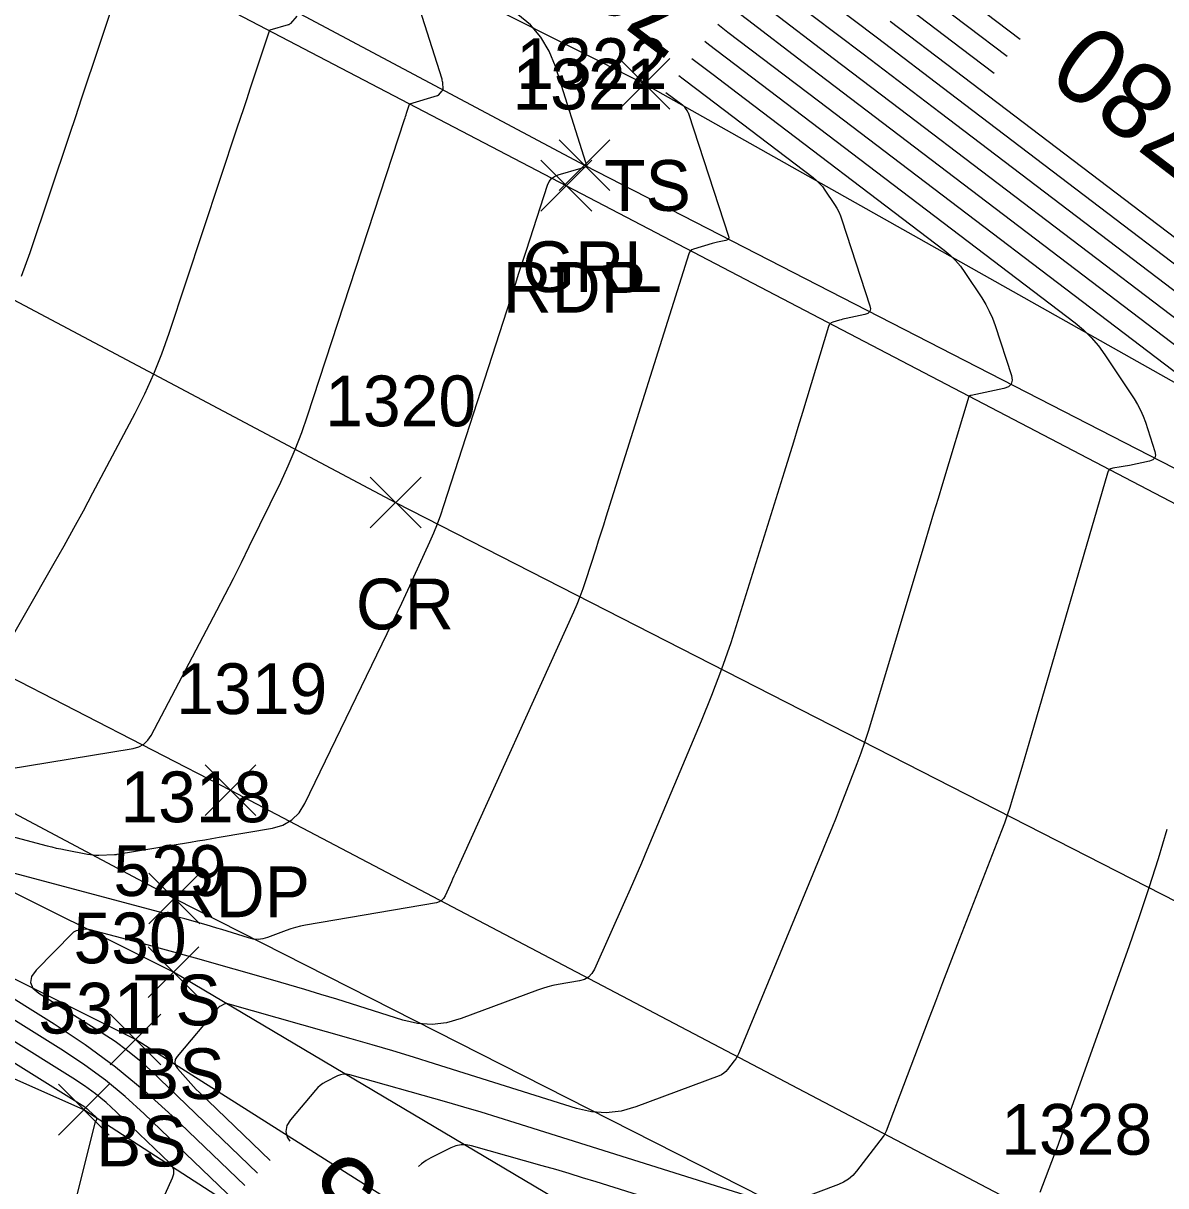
# Model space of a CAD drawing. Extents: x 1650836 to 1652450, y 332578 to 333908.
# Drawn here: x 1652324.34 to 1652369.33, y 332642.95 to 332688.73 of the extents above; entities that cross this region are included whole.
import ezdxf

# ---------------------------------------------------------------- set-up
doc = ezdxf.new("R2010")
doc.units = 0
for name, color, linetype in [('L_A', 7, 'Continuous'), ('L_I', 7, 'Continuous'), ('L_TIC', 7, 'Continuous'), ('LAWA', 7, 'Continuous'), ('LELB', 7, 'Continuous'), ('LSOGCMA', 7, 'Continuous'), ('LSOGCMA_T', 7, 'Continuous'), ('LSOGCMI', 7, 'Continuous'), ('P_A', 7, 'Continuous'), ('P_I', 7, 'Continuous'), ('P_TIC', 7, 'Continuous'), ('PET', 7, 'Continuous'), ('PRC', 7, 'Continuous'), ('R_A', 7, 'Continuous'), ('R_I', 7, 'Continuous'), ('R_TIC', 7, 'Continuous'), ('RGR', 7, 'Continuous')]:
    doc.layers.add(name, color=color, linetype=linetype)

msp = doc.modelspace()

# ---------------------------------------------------------------- linework, layer by layer
at = {"layer": 'L_TIC'}
for points in [[(1652347.8, 332685.345), (1652349.8, 332687.345)], [(1652349.8, 332685.345), (1652347.8, 332687.345)], [(1652329.286, 332653.264), (1652331.286, 332655.264)], [(1652331.286, 332653.264), (1652329.286, 332655.264)], [(1652329.255, 332650.361), (1652331.255, 332652.361)], [(1652331.255, 332650.361), (1652329.255, 332652.361)], [(1652327.76, 332647.708), (1652329.76, 332649.708)], [(1652329.76, 332647.708), (1652327.76, 332649.708)], [(1652325.723, 332644.943), (1652327.723, 332646.943)], [(1652327.723, 332644.943), (1652325.723, 332646.943)]]:
    msp.add_lwpolyline(points, dxfattribs=at)
at = {"layer": 'LAWA'}
msp.add_lwpolyline([(1652377.083, 332609.462), (1652362.423, 332618.359), (1652352.896, 332629.018), (1652326.723, 332645.943), (1652287.129, 332663.549), (1652263.425, 332671.343), (1652249.055, 332682.968), (1652227.219, 332684.809), (1652198.28, 332683.973), (1652188.25, 332681.448)], dxfattribs=at)
at = {"layer": 'LELB'}
for points in [[(1652023.441, 332859.649), (1652034.235, 332853.429), (1652052.246, 332842.357), (1652084.686, 332826.36), (1652123.711, 332804.04), (1652160.81, 332785.384), (1652195.281, 332767.897), (1652235.573, 332746.682), (1652255.289, 332735.81), (1652296.57, 332712.591), (1652348.8, 332686.345), (1652380.841, 332668.301), (1652404.073, 332656.539)], [(1652226.417, 332702.923), (1652236.723, 332699.587), (1652280.373, 332680.816), (1652330.286, 332654.264), (1652363.786, 332637.255), (1652386.916, 332625.064)], [(1652382.141, 332616.979), (1652358.657, 332634.506), (1652330.255, 332651.361), (1652290.321, 332671.283), (1652269.989, 332681.007), (1652251.521, 332688.043), (1652226.806, 332692.532), (1652196.733, 332693.642), (1652183.53, 332688.882)], [(1652365.04, 332620.431), (1652356.315, 332631.256), (1652328.76, 332648.708), (1652289.164, 332668.483), (1652266.826, 332677.17), (1652249.055, 332682.968)]]:
    msp.add_lwpolyline(points, dxfattribs=at)
at = {"layer": 'LSOGCMA'}
for points in [[(1652351.174, 332688.023), (1652351.321, 332687.911), (1652352.688, 332686.871), (1652354.055, 332685.831), (1652365.761, 332676.93), (1652366.093, 332676.654), (1652366.399, 332676.354), (1652366.678, 332676.03), (1652366.931, 332675.68), (1652368.085, 332673.937), (1652368.219, 332673.718), (1652368.337, 332673.493), (1652368.44, 332673.26), (1652368.528, 332673.019), (1652368.906, 332671.862), (1652368.93, 332671.723), (1652368.902, 332671.614), (1652368.822, 332671.535), (1652368.689, 332671.486), (1652367.901, 332671.319), (1652367.819, 332671.302), (1652367.737, 332671.286), (1652367.655, 332671.271), (1652367.573, 332671.257), (1652367.244, 332671.204), (1652367.169, 332671.182), (1652367.109, 332671.143), (1652367.064, 332671.088), (1652367.033, 332671.017), (1652364.032, 332660.683), (1652363.94, 332660.368), (1652363.847, 332660.053), (1652363.754, 332659.738), (1652363.66, 332659.424), (1652363.285, 332658.166), (1652363.188, 332657.852), (1652363.084, 332657.541), (1652362.975, 332657.232), (1652362.859, 332656.924), (1652361.118, 332652.433), (1652360.831, 332651.689), (1652360.545, 332650.945), (1652360.26, 332650.201), (1652359.976, 332649.456), (1652358.32, 332645.096), (1652358.297, 332645.042), (1652358.271, 332644.989), (1652358.24, 332644.939), (1652358.206, 332644.891), (1652357.151, 332643.516), (1652357.001, 332643.347), (1652356.833, 332643.203), (1652356.646, 332643.084), (1652356.441, 332642.992), (1652354.838, 332642.395)], [(1652353.47, 332642.359), (1652343.712, 332645.427), (1652343.039, 332645.636), (1652342.364, 332645.841), (1652341.689, 332646.04), (1652341.012, 332646.235), (1652337.196, 332647.32), (1652337.071, 332647.343), (1652336.949, 332647.344), (1652336.83, 332647.32), (1652336.712, 332647.273), (1652336.248, 332647.036), (1652336.136, 332646.971), (1652336.032, 332646.897), (1652335.936, 332646.812), (1652335.848, 332646.717), (1652334.864, 332645.543), (1652334.721, 332645.315), (1652334.675, 332645.088), (1652334.727, 332644.863), (1652334.834, 332644.702)]]:
    msp.add_lwpolyline(points, dxfattribs=at)
at = {"layer": 'LSOGCMI'}
for points in [[(1652324.267, 332678.777), (1652324.604, 332679.706), (1652326.168, 332684.369), (1652326.401, 332685.066), (1652326.634, 332685.763), (1652326.866, 332686.46), (1652327.099, 332687.157), (1652328.479, 332691.305)], [(1652323.707, 332659.351), (1652328.661, 332660.175), (1652328.885, 332660.237), (1652329.078, 332660.343), (1652329.239, 332660.493), (1652329.369, 332660.686), (1652331.962, 332665.607), (1652332.288, 332666.233), (1652332.61, 332666.862), (1652332.926, 332667.492), (1652333.238, 332668.126), (1652334.474, 332670.664), (1652334.772, 332671.304), (1652335.047, 332671.952), (1652335.301, 332672.609), (1652335.532, 332673.275), (1652339.355, 332684.944), (1652339.375, 332685.006), (1652339.395, 332685.067), (1652339.415, 332685.129), (1652339.435, 332685.19), (1652339.552, 332685.55), (1652339.554, 332685.554), (1652339.557, 332685.557), (1652339.561, 332685.56), (1652339.565, 332685.562), (1652340.656, 332685.883), (1652340.669, 332685.888), (1652340.682, 332685.895), (1652340.693, 332685.903), (1652340.703, 332685.913), (1652340.825, 332686.056), (1652340.845, 332686.085), (1652340.859, 332686.115), (1652340.867, 332686.148), (1652340.868, 332686.183), (1652340.858, 332686.362), (1652340.854, 332686.404), (1652340.848, 332686.445), (1652340.839, 332686.486), (1652340.828, 332686.526), (1652339.757, 332689.916)], [(1652380.189, 332669.134), (1652358.847, 332685.363), (1652356.233, 332687.351), (1652353.62, 332689.34), (1652352.707, 332690.035)], [(1652376.091, 332674.367), (1652360.799, 332685.996), (1652357.975, 332688.144), (1652355.153, 332690.292)], [(1652359.485, 332690.171), (1652361.52, 332688.624), (1652363.081, 332687.437)], [(1652378.14, 332671.75), (1652360.444, 332685.207), (1652357.415, 332687.511), (1652354.387, 332689.816)], [(1652358.982, 332689.495), (1652361.279, 332687.748), (1652362.568, 332686.768)], [(1652361.76, 332689.499), (1652363.593, 332688.106)], [(1652315.11, 332659.045), (1652325.279, 332656.339), (1652325.458, 332656.293), (1652325.637, 332656.25), (1652325.818, 332656.211), (1652325.999, 332656.174), (1652326.867, 332656.007), (1652326.978, 332655.989), (1652327.089, 332655.977), (1652327.2, 332655.972), (1652327.313, 332655.972), (1652327.935, 332655.992), (1652327.961, 332655.993), (1652327.986, 332655.995), (1652328.012, 332655.998), (1652328.038, 332656.002), (1652330.922, 332656.482), (1652331.203, 332656.529), (1652331.483, 332656.576), (1652331.764, 332656.624), (1652332.045, 332656.672), (1652334.15, 332657.036), (1652334.563, 332657.154), (1652334.914, 332657.354), (1652335.204, 332657.636), (1652335.431, 332658.001), (1652339.077, 332665.544), (1652339.241, 332665.888), (1652339.404, 332666.233), (1652339.564, 332666.579), (1652339.723, 332666.925), (1652340.351, 332668.315), (1652340.503, 332668.664), (1652340.646, 332669.017), (1652340.778, 332669.374), (1652340.9, 332669.735), (1652343.535, 332677.888), (1652343.69, 332678.366), (1652343.845, 332678.845), (1652344, 332679.323), (1652344.155, 332679.801), (1652344.986, 332682.356), (1652345.05, 332682.499), (1652345.141, 332682.614), (1652345.259, 332682.702), (1652345.404, 332682.762), (1652346.307, 332683.028), (1652346.372, 332683.047), (1652346.528, 332683.093), (1652346.537, 332683.095), (1652346.539, 332683.096), (1652346.539, 332683.098), (1652346.509, 332683.189), (1652346.499, 332683.221), (1652346.489, 332683.252), (1652345.294, 332687.036), (1652345.05, 332687.641), (1652344.722, 332688.185), (1652344.307, 332688.666), (1652343.808, 332689.085)], [(1652335.109, 332689.018), (1652334.862, 332688.729), (1652334.842, 332688.709), (1652334.82, 332688.692), (1652334.795, 332688.678), (1652334.768, 332688.668), (1652334.051, 332688.457), (1652334.038, 332688.452), (1652334.028, 332688.444), (1652334.019, 332688.434), (1652334.014, 332688.421), (1652333.262, 332686.137), (1652333.135, 332685.752), (1652333.008, 332685.366), (1652332.881, 332684.981), (1652332.753, 332684.596), (1652330.073, 332676.508), (1652329.786, 332675.702), (1652329.468, 332674.909), (1652329.116, 332674.131), (1652328.732, 332673.367), (1652327.067, 332670.221), (1652326.694, 332669.523), (1652326.315, 332668.829), (1652325.93, 332668.138), (1652325.539, 332667.45), (1652323.353, 332663.638)], [(1652376.202, 332671.107), (1652357.25, 332685.519), (1652355.051, 332687.191), (1652352.854, 332688.864), (1652352.196, 332689.364)], [(1652351.685, 332688.694), (1652352.087, 332688.387), (1652353.87, 332687.031), (1652355.652, 332685.675), (1652370.917, 332674.067)], [(1652358.479, 332688.819), (1652361.039, 332686.872), (1652374.043, 332676.984)], [(1652350.663, 332687.352), (1652351.506, 332686.711), (1652352.457, 332685.987), (1652360.605, 332679.792), (1652360.836, 332679.6), (1652361.049, 332679.391), (1652361.243, 332679.165), (1652361.419, 332678.922), (1652362.086, 332677.914), (1652362.244, 332677.658), (1652362.383, 332677.393), (1652362.504, 332677.119), (1652362.607, 332676.836), (1652363.252, 332674.861), (1652363.285, 332674.671), (1652363.247, 332674.522), (1652363.137, 332674.414), (1652362.956, 332674.347), (1652361.672, 332674.074), (1652361.663, 332674.072), (1652361.654, 332674.07), (1652361.645, 332674.068), (1652361.636, 332674.065), (1652361.6, 332674.055), (1652361.592, 332674.051), (1652361.586, 332674.046), (1652361.581, 332674.04), (1652361.577, 332674.032), (1652360.536, 332670.589), (1652360.362, 332670.013), (1652360.188, 332669.436), (1652360.015, 332668.859), (1652359.842, 332668.282), (1652357.747, 332661.27), (1652357.614, 332660.839), (1652357.472, 332660.411), (1652357.321, 332659.985), (1652357.162, 332659.563), (1652356.509, 332657.878), (1652356.345, 332657.457), (1652356.178, 332657.038), (1652356.009, 332656.619), (1652355.838, 332656.201), (1652352.55, 332648.235), (1652352.506, 332648.137), (1652352.456, 332648.043), (1652352.4, 332647.953), (1652352.337, 332647.865), (1652352.075, 332647.524), (1652352.005, 332647.444), (1652351.926, 332647.377), (1652351.839, 332647.322), (1652351.742, 332647.278), (1652348.462, 332646.057), (1652347.88, 332645.891), (1652347.296, 332645.826), (1652346.709, 332645.861), (1652346.12, 332645.996), (1652340.527, 332647.754), (1652339.711, 332648.008), (1652338.893, 332648.256), (1652338.073, 332648.498), (1652337.252, 332648.735), (1652332.396, 332650.114), (1652332.358, 332650.122), (1652332.32, 332650.122), (1652332.283, 332650.114), (1652332.247, 332650.1), (1652332.104, 332650.027), (1652332.069, 332650.007), (1652332.037, 332649.984), (1652332.007, 332649.958), (1652331.98, 332649.929), (1652330.399, 332648.042), (1652330.323, 332647.921), (1652330.299, 332647.801), (1652330.327, 332647.681), (1652330.406, 332647.562), (1652330.826, 332647.089), (1652330.932, 332646.971), (1652331.04, 332646.856), (1652331.151, 332646.743), (1652331.264, 332646.633), (1652334.066, 332643.943)], [(1652350.152, 332686.682), (1652350.324, 332686.551), (1652350.86, 332686.143), (1652355.449, 332682.654), (1652355.579, 332682.546), (1652355.699, 332682.428), (1652355.808, 332682.301), (1652355.907, 332682.164), (1652356.283, 332681.596), (1652356.372, 332681.452), (1652356.45, 332681.303), (1652356.519, 332681.148), (1652356.577, 332680.989), (1652357.681, 332677.607), (1652357.703, 332677.48), (1652357.677, 332677.38), (1652357.604, 332677.308), (1652357.483, 332677.263), (1652356.746, 332677.107), (1652356.68, 332677.092), (1652356.613, 332677.076), (1652356.547, 332677.058), (1652356.481, 332677.039), (1652356.217, 332676.961), (1652356.157, 332676.936), (1652356.109, 332676.899), (1652356.072, 332676.85), (1652356.046, 332676.791), (1652355.021, 332673.401), (1652354.843, 332672.815), (1652354.664, 332672.228), (1652354.483, 332671.642), (1652354.302, 332671.057), (1652352.536, 332665.379), (1652352.196, 332664.33), (1652351.832, 332663.291), (1652351.442, 332662.261), (1652351.028, 332661.24), (1652348.899, 332656.162), (1652348.683, 332655.651), (1652348.464, 332655.142), (1652348.242, 332654.633), (1652348.017, 332654.126), (1652346.832, 332651.474), (1652346.73, 332651.301), (1652346.597, 332651.166), (1652346.434, 332651.071), (1652346.24, 332651.015), (1652345.404, 332650.871), (1652345.196, 332650.83), (1652344.991, 332650.779), (1652344.789, 332650.72), (1652344.589, 332650.65), (1652341.579, 332649.53), (1652341.009, 332649.368), (1652340.438, 332649.304), (1652339.863, 332649.338), (1652339.287, 332649.47), (1652336.68, 332650.29), (1652336.052, 332650.485), (1652335.423, 332650.676), (1652334.793, 332650.862), (1652334.161, 332651.044), (1652331.113, 332651.91), (1652330.688, 332652.03), (1652330.263, 332652.148), (1652329.837, 332652.264), (1652329.41, 332652.378), (1652326.97, 332653.028), (1652326.91, 332653.041), (1652326.849, 332653.047), (1652326.788, 332653.047), (1652326.727, 332653.041), (1652326.481, 332653.004), (1652326.422, 332652.99), (1652326.367, 332652.967), (1652326.317, 332652.936), (1652326.271, 332652.896), (1652324.842, 332651.434), (1652324.659, 332651.184), (1652324.616, 332650.951), (1652324.713, 332650.734), (1652324.95, 332650.534), (1652327.444, 332648.975), (1652327.952, 332648.639), (1652328.441, 332648.278), (1652328.911, 332647.892), (1652329.361, 332647.482), (1652333.564, 332643.448)], [(1652349.642, 332686.011), (1652350.293, 332685.516), (1652350.322, 332685.492), (1652350.349, 332685.465), (1652350.373, 332685.437), (1652350.396, 332685.406), (1652350.48, 332685.279), (1652350.5, 332685.246), (1652350.518, 332685.213), (1652350.533, 332685.178), (1652350.546, 332685.142), (1652352.11, 332680.353), (1652352.121, 332680.288), (1652352.108, 332680.238), (1652352.071, 332680.202), (1652352.01, 332680.179), (1652351.68, 332680.109), (1652351.625, 332680.097), (1652351.571, 332680.084), (1652351.518, 332680.07), (1652351.464, 332680.054), (1652350.728, 332679.836), (1652350.664, 332679.809), (1652350.613, 332679.77), (1652350.573, 332679.719), (1652350.545, 332679.656), (1652347.282, 332669.281), (1652347.183, 332668.966), (1652347.083, 332668.652), (1652346.983, 332668.338), (1652346.882, 332668.024), (1652346.476, 332666.769), (1652346.37, 332666.457), (1652346.256, 332666.148), (1652346.133, 332665.843), (1652346.001, 332665.54), (1652341.346, 332655.248), (1652341.296, 332655.138), (1652341.246, 332655.027), (1652341.196, 332654.916), (1652341.146, 332654.805), (1652340.948, 332654.36), (1652340.889, 332654.261), (1652340.813, 332654.183), (1652340.72, 332654.129), (1652340.609, 332654.097), (1652335.447, 332653.205), (1652335.255, 332653.168), (1652335.064, 332653.121), (1652334.876, 332653.065), (1652334.691, 332653.001), (1652333.953, 332652.726), (1652333.768, 332652.674), (1652333.582, 332652.653), (1652333.396, 332652.664), (1652333.209, 332652.707), (1652332.362, 332652.973), (1652332.158, 332653.037), (1652331.954, 332653.099), (1652331.749, 332653.159), (1652331.544, 332653.218), (1652330.698, 332653.459), (1652330.488, 332653.518), (1652330.278, 332653.576), (1652330.068, 332653.633), (1652329.857, 332653.69), (1652321.04, 332656.037)], [(1652297.877, 332664.113), (1652326.661, 332646.12), (1652326.726, 332646.078), (1652326.788, 332646.032), (1652326.847, 332645.983), (1652326.905, 332645.931), (1652327.204, 332645.643), (1652327.219, 332645.625), (1652327.226, 332645.605), (1652327.226, 332645.584), (1652327.22, 332645.562), (1652327.178, 332645.469), (1652327.168, 332645.446), (1652327.159, 332645.422), (1652327.151, 332645.398), (1652327.145, 332645.374), (1652325.086, 332637.108)], [(1652329.921, 332642.614), (1652330.215, 332643.264), (1652330.263, 332643.422), (1652330.261, 332643.57), (1652330.208, 332643.708), (1652330.105, 332643.837), (1652328.001, 332645.855), (1652327.599, 332646.222), (1652327.18, 332646.566), (1652326.743, 332646.888), (1652326.29, 332647.189), (1652304.645, 332660.718)], [(1652333.005, 332642.03), (1652329.098, 332645.78), (1652328.351, 332646.461), (1652327.572, 332647.101), (1652326.761, 332647.699), (1652325.918, 332648.257), (1652311.413, 332657.324)], [(1652369.368, 332656.985), (1652369.027, 332655.829), (1652368.668, 332654.68), (1652368.29, 332653.537), (1652367.894, 332652.399), (1652365.485, 332645.656), (1652365.35, 332645.282), (1652365.214, 332644.909), (1652365.075, 332644.536), (1652364.935, 332644.164), (1652364.37, 332642.677)], [(1652318.181, 332653.929), (1652325.547, 332649.325), (1652326.779, 332648.51), (1652327.964, 332647.635), (1652329.103, 332646.7), (1652330.195, 332645.704), (1652333.062, 332642.952)], [(1652360.821, 332638.723), (1652346.896, 332643.1), (1652346.367, 332643.265), (1652345.836, 332643.426), (1652345.304, 332643.583), (1652344.771, 332643.736), (1652341.995, 332644.525), (1652341.785, 332644.565), (1652341.579, 332644.565), (1652341.376, 332644.525), (1652341.178, 332644.445), (1652340.392, 332644.044), (1652340.202, 332643.936), (1652340.026, 332643.81), (1652339.907, 332643.704)]]:
    msp.add_lwpolyline(points, dxfattribs=at)
at = {"layer": 'P_TIC'}
for points in [[(1652344.726, 332681.336), (1652346.726, 332683.336)], [(1652346.726, 332681.336), (1652344.726, 332683.336)], [(1652338.002, 332668.86), (1652340.002, 332670.86)], [(1652340.002, 332668.86), (1652338.002, 332670.86)], [(1652331.494, 332657.525), (1652333.494, 332659.525)], [(1652333.494, 332657.525), (1652331.494, 332659.525)]]:
    msp.add_lwpolyline(points, dxfattribs=at)
at = {"layer": 'PET'}
for points in [[(1651782.185, 332994.087), (1651800.504, 332980.945), (1651823.969, 332965.234), (1651861.092, 332941.311), (1651895.497, 332920.881), (1651932.1, 332899.878), (1651964.344, 332882.546), (1651997.084, 332865.287), (1652030.302, 332847.665), (1652049.548, 332837.673), (1652081.974, 332820.953), (1652121.026, 332800.401), (1652157.819, 332781.161), (1652191.945, 332763.077), (1652232.596, 332742.33), (1652251.93, 332731.59), (1652295.202, 332708.727), (1652345.726, 332682.336), (1652379.152, 332664.868), (1652402.111, 332652.828)], [(1651764.546, 332972.615), (1651784.506, 332958.597), (1651809.702, 332941.927), (1651846.26, 332918.158), (1651881.765, 332897.162), (1651918.116, 332876.642), (1651951.432, 332858.415), (1651975.296, 332845.48), (1652002.223, 332831.337), (1652037.173, 332813.417), (1652069.296, 332796.636), (1652107.428, 332776.545), (1652145.079, 332756.921), (1652175.234, 332740.226), (1652190.754, 332731.861), (1652206.573, 332723.523), (1652239.422, 332706.921), (1652282.404, 332684.366), (1652332.494, 332658.525), (1652365.542, 332641.171), (1652388.914, 332629.021)]]:
    msp.add_lwpolyline(points, dxfattribs=at)
at = {"layer": 'PRC'}
msp.add_lwpolyline([(1651773.612, 332982.822), (1651792.672, 332969.525), (1651816.542, 332953.47), (1651853.779, 332929.89), (1651888.829, 332909.027), (1651925.09, 332888.189), (1651957.726, 332870.48), (1651982.519, 332857.297), (1652019.654, 332837.681), (1652042.767, 332825.192), (1652076.048, 332808.311), (1652114.48, 332787.851), (1652150.944, 332769.103), (1652185.791, 332750.516), (1652225.777, 332729.89), (1652246.28, 332718.635), (1652288.707, 332696.529), (1652339.002, 332669.86), (1652372.556, 332652.699), (1652395.364, 332640.33)], dxfattribs=at)
at = {"layer": 'R_TIC'}
for points in [[(1652345.443, 332682.145), (1652347.443, 332684.145)], [(1652347.443, 332682.145), (1652345.443, 332684.145)]]:
    msp.add_lwpolyline(points, dxfattribs=at)
at = {"layer": 'RGR'}
msp.add_lwpolyline([(1652023.441, 332859.649), (1652024.915, 332854.382), (1652030.806, 332848.332), (1652049.928, 332838.521), (1652082.838, 332821.514), (1652121.63, 332801.012), (1652157.949, 332781.905), (1652192.709, 332763.821), (1652232.753, 332742.853), (1652252.846, 332732.22), (1652295.713, 332710.152), (1652346.443, 332683.145), (1652379.801, 332666.008), (1652402.772, 332654.006)], dxfattribs=at)

# ---------------------------------------------------------------- texts
at = {"layer": 'L_A'}
for s, p in [('TS', (1652347.21, 332681.345)), ('TS', (1652328.695, 332649.264)), ('BS', (1652328.696, 332646.361)), ('BS', (1652327.201, 332643.708))]:
    msp.add_text(s, height=2, dxfattribs=at).set_placement(p)
at = {"layer": 'L_I'}
for s, p in [('1318', (1652328.16, 332657.264)), ('529', (1652327.885, 332654.361)), ('530', (1652326.312, 332651.708)), ('531', (1652324.927, 332648.943))]:
    msp.add_text(s, height=2, dxfattribs=at).set_placement(p)
at = {"layer": 'LSOGCMA_T'}
for s, rotation, p in [('785', 142.6979, (1652351.548, 332689.625)), ('780', 142.5292, (1652371.734, 332684.825)), ('785', 134.6313, (1652341.687, 332639.766))]:
    msp.add_text(s, height=3, rotation=rotation, dxfattribs=at).set_placement(p)
at = {"layer": 'P_A'}
for s, p in [('RDP', (1652343.214, 332677.336)), ('CR', (1652337.435, 332664.86)), ('RDP', (1652329.982, 332653.525))]:
    msp.add_text(s, height=2, dxfattribs=at).set_placement(p)
at = {"layer": 'P_I'}
for s, p in [('1321', (1652343.6, 332685.336)), ('1320', (1652336.223, 332672.86)), ('1319', (1652330.361, 332661.525)), ('1328', (1652362.849, 332644.171))]:
    msp.add_text(s, height=2, dxfattribs=at).set_placement(p)
at = {"layer": 'R_A'}
msp.add_text('GRL', height=2, dxfattribs=at).set_placement((1652343.987, 332678.145))
at = {"layer": 'R_I'}
msp.add_text('1322', height=2, dxfattribs=at).set_placement((1652343.751, 332686.145))

doc.saveas('drawing.dxf')
